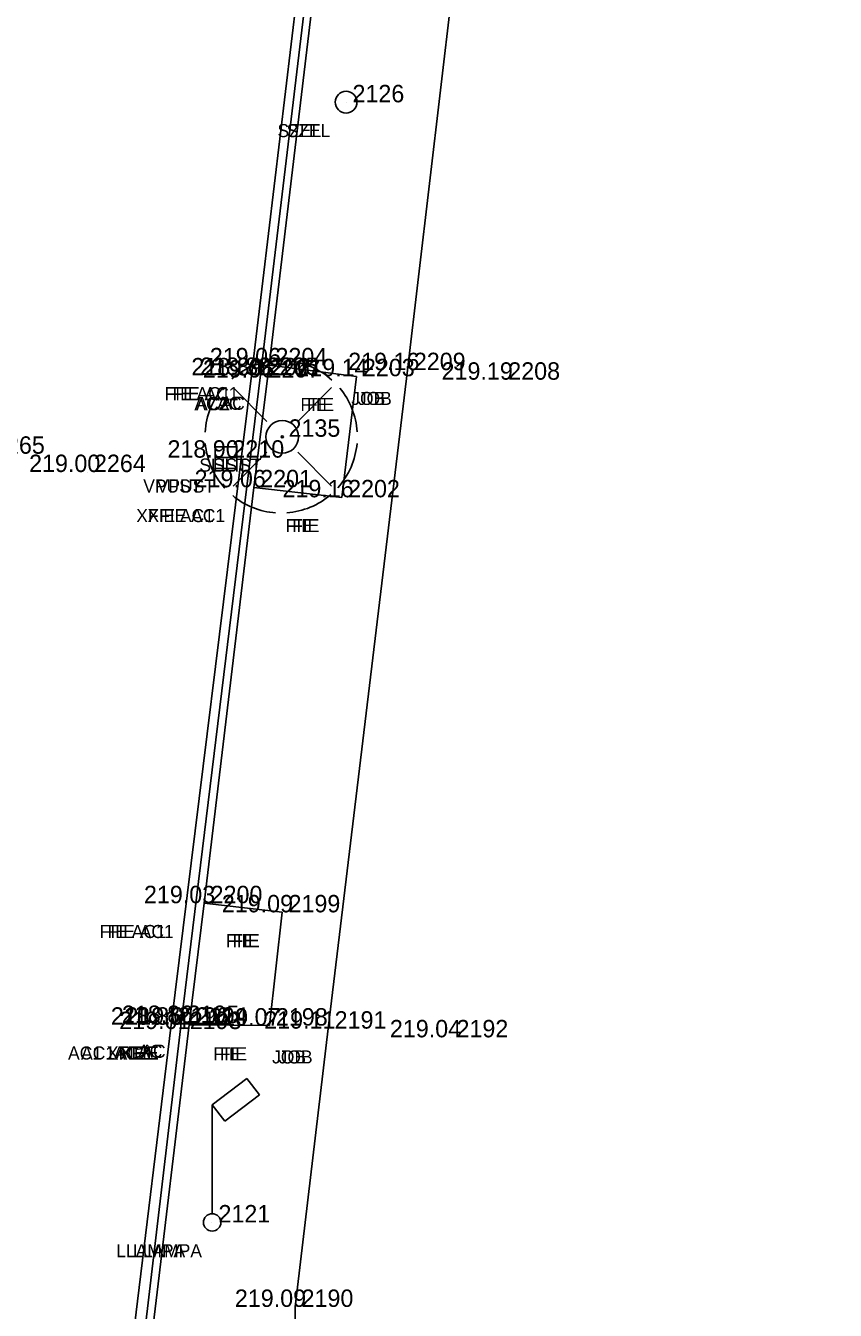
# Model space of a CAD drawing. Extents: x -471047 to -470889, y -1102859 to -1102000.
# Drawn here: x -470938.1 to -470919.5, y -1102294.05 to -1102264.55 of the extents above; entities that cross this region are included whole.
import ezdxf

# ---------------------------------------------------------------- set-up
doc = ezdxf.new("R2010")
doc.units = 0
for name, color, linetype in [('Vrstva 1', 7, 'Continuous'), ('Vrstva 16', 7, 'Continuous'), ('Vrstva 23', 7, 'Continuous'), ('Vrstva 25', 7, 'Continuous'), ('Vrstva 34', 7, 'Continuous'), ('Vrstva 35', 7, 'Continuous'), ('Vrstva 36', 7, 'Continuous'), ('Vrstva 38', 7, 'Continuous'), ('Vrstva 5', 7, 'Continuous'), ('Vrstva 7', 7, 'Continuous'), ('Vrstva 8', 7, 'Continuous')]:
    doc.layers.add(name, color=color, linetype=linetype)

msp = doc.modelspace()

# ---------------------------------------------------------------- linework, layer by layer
at = {"layer": 'Vrstva 1'}
for points in [[(-471040.344, -1102858.385), (-471031.676, -1102846.187), (-471026.357, -1102838.629), (-471023.212, -1102833.975), (-471019.21, -1102827.465), (-471016.861, -1102823.272), (-471013.099, -1102815.912), (-471010.824, -1102810.955), (-471007.329, -1102802.292), (-471005.34, -1102796.515), (-471002.842, -1102787.838), (-471001.3, -1102780.997), (-471000.19, -1102774.713), (-470999.247, -1102768.204), (-470998.794, -1102764.784), (-470997.199, -1102751.812), (-470994.899, -1102732.807), (-470992.551, -1102713.262), (-470990.326, -1102694.887), (-470988.122, -1102676.57), (-470985.812, -1102657.305), (-470983.537, -1102638.407), (-470981.386, -1102620.622), (-470979.843, -1102608.014), (-470976.377, -1102579.253), (-470972.945, -1102550.69), (-470970.475, -1102530.206), (-470967.905, -1102508.801), (-470965.053, -1102485.131), (-470962.734, -1102465.9), (-470960.173, -1102444.812), (-470957.795, -1102425.103), (-470954.965, -1102401.839), (-470953.834, -1102392.574), (-470952.33, -1102379.985), (-470950.744, -1102366.853), (-470948.978, -1102352.106), (-470947.037, -1102335.844), (-470944.949, -1102318.462), (-470944.013, -1102310.745), (-470942.39, -1102297.267), (-470939.519, -1102273.45), (-470937.593, -1102257.43), (-470936.064, -1102244.81), (-470934.114, -1102228.634), (-470931.621, -1102207.856), (-470929.536, -1102190.857), (-470926.572, -1102166.31), (-470924.91, -1102152.663), (-470923.413, -1102140.333), (-470921.923, -1102127.669), (-470921.155, -1102120.084), (-470920.446, -1102109.574), (-470919.912, -1102099.137), (-470919.63, -1102088.981), (-470919.523, -1102081.193), (-470919.563, -1102070.395), (-470919.714, -1102064.236), (-470920.134, -1102054.704), (-470920.462, -1102047.615), (-470920.599, -1102044.52), (-470920.743, -1102041.873), (-470921.125, -1102034.455), (-470921.774, -1102030.337), (-470922.418, -1102027.787), (-470923.734, -1102023.93), (-470924.872, -1102021.434), (-470926.752, -1102018.182), (-470927.953, -1102016.45), (-470929.616, -1102014.424), (-470932.252, -1102011.756), (-470935.111, -1102009.425), (-470938.391, -1102007.371), (-470942.651, -1102005.401)], [(-471041.328, -1102857.18), (-471032.144, -1102844.242), (-471027.583, -1102837.763), (-471024.388, -1102833.028), (-471020.451, -1102826.6), (-471018.089, -1102822.378), (-471014.542, -1102815.445), (-471012.233, -1102810.418), (-471009.247, -1102803.108), (-471006.795, -1102796.098), (-471004.315, -1102787.532), (-471002.782, -1102780.723), (-471001.674, -1102774.458), (-471000.75, -1102768.095), (-471000.28, -1102764.601), (-470998.692, -1102751.741), (-470996.378, -1102732.635), (-470994.028, -1102713.058), (-470991.808, -1102694.749), (-470989.616, -1102676.447), (-470987.284, -1102657.013), (-470985.031, -1102638.272), (-470982.87, -1102620.431), (-470981.334, -1102607.933), (-470977.881, -1102579.263), (-470974.429, -1102550.492), (-470971.964, -1102530.054), (-470969.391, -1102508.607), (-470966.54, -1102484.984), (-470964.231, -1102465.853), (-470961.679, -1102444.752), (-470959.304, -1102425.078), (-470956.455, -1102401.634), (-470955.339, -1102392.489), (-470953.812, -1102379.71), (-470952.249, -1102366.808), (-470950.479, -1102352.023), (-470948.536, -1102335.868), (-470946.426, -1102318.233), (-470945.493, -1102310.531), (-470943.864, -1102297.013), (-470940.984, -1102273.071), (-470939.078, -1102257.195), (-470937.559, -1102244.684), (-470935.592, -1102228.353), (-470933.101, -1102207.653), (-470931.011, -1102190.57), (-470928.046, -1102166.021), (-470926.409, -1102152.578), (-470924.898, -1102140.121), (-470923.427, -1102127.544), (-470922.647, -1102119.826), (-470921.919, -1102109.229), (-470921.42, -1102099.134), (-470921.127, -1102089.016), (-470921.023, -1102081.453), (-470921.061, -1102070.468), (-470921.209, -1102064.314), (-470921.666, -1102053.966), (-470922.156, -1102043.345), (-470922.299, -1102039.934), (-470922.637, -1102034.36), (-470923.091, -1102031.241), (-470923.847, -1102028.247), (-470925.083, -1102024.594), (-470926.222, -1102022.086), (-470928.04, -1102018.943), (-470929.138, -1102017.357), (-470930.929, -1102015.175), (-470933.062, -1102013.049), (-470936.379, -1102010.368), (-470939.169, -1102008.662), (-470942.899, -1102006.906), (-470945.661, -1102005.908)], [(-471043.557, -1102855.955), (-471035.129, -1102844.026), (-471029.872, -1102836.499), (-471026.577, -1102831.578), (-471022.675, -1102825.415), (-471020.123, -1102821.053), (-471016.667, -1102814.59), (-471014.208, -1102809.45), (-471011.177, -1102802.451), (-471008.55, -1102795.333), (-471006.082, -1102787.209), (-471004.464, -1102780.376), (-471003.265, -1102774.167), (-471002.327, -1102767.948), (-471001.636, -1102762.527), (-471000.297, -1102751.605), (-470997.959, -1102732.524), (-470995.602, -1102712.802), (-470993.412, -1102694.623), (-470991.21, -1102676.17), (-470988.891, -1102656.857), (-470986.625, -1102638.083), (-470984.455, -1102620.195), (-470982.936, -1102607.733), (-470979.497, -1102579.223), (-470976.023, -1102550.279), (-470973.554, -1102529.822), (-470970.991, -1102508.497), (-470968.146, -1102484.787), (-470965.835, -1102465.72), (-470963.284, -1102444.529), (-470960.91, -1102424.942), (-470958.043, -1102401.343), (-470956.946, -1102392.356), (-470955.396, -1102379.408), (-470953.851, -1102366.636), (-470952.049, -1102351.733), (-470950.124, -1102335.611), (-470948.034, -1102318.083), (-470947.094, -1102310.328), (-470945.421, -1102296.51), (-470942.58, -1102272.848), (-470940.675, -1102256.948), (-470939.176, -1102244.526), (-470937.187, -1102228.174), (-470934.708, -1102207.467), (-470932.621, -1102190.433), (-470929.634, -1102165.778), (-470928.004, -1102152.415), (-470926.45, -1102139.595), (-470925.003, -1102127.418), (-470924.249, -1102119.695), (-470923.515, -1102109.093), (-470923.018, -1102099.069), (-470922.711, -1102088.911), (-470922.643, -1102081.356), (-470922.797, -1102070.414), (-470923.018, -1102064.454), (-470923.52, -1102053.203), (-470923.823, -1102047.529), (-470924.123, -1102041.506), (-470924.462, -1102037.486), (-470924.934, -1102031.904), (-470925.664, -1102028.672), (-470926.771, -1102025.506), (-470927.959, -1102022.914), (-470929.674, -1102020.028), (-470930.76, -1102018.498), (-470932.447, -1102016.478), (-470935.215, -1102013.816), (-470937.644, -1102011.98), (-470940.381, -1102010.371), (-470943.968, -1102008.669), (-470947.145, -1102007.524), (-470950.874, -1102006.74)], [(-471044.756, -1102855.056), (-471036.376, -1102843.177), (-471031.167, -1102835.741), (-471027.859, -1102830.8), (-471023.934, -1102824.593), (-471021.43, -1102820.312), (-471018.011, -1102813.91), (-471015.536, -1102808.75), (-471012.578, -1102801.897), (-471009.95, -1102794.77), (-471007.561, -1102786.914), (-471005.936, -1102780.074), (-471004.727, -1102773.818), (-471003.828, -1102767.827), (-471003.121, -1102762.345), (-471001.787, -1102751.467), (-470999.446, -1102732.348), (-470997.073, -1102712.539), (-470994.902, -1102694.521), (-470992.696, -1102676.023), (-470990.376, -1102656.68), (-470988.131, -1102638.071), (-470985.947, -1102620.018), (-470984.417, -1102607.512), (-470980.993, -1102579.08), (-470977.514, -1102550.137), (-470975.048, -1102529.649), (-470972.488, -1102508.37), (-470969.618, -1102484.508), (-470967.34, -1102465.669), (-470964.767, -1102444.39), (-470962.402, -1102424.781), (-470959.534, -1102401.193), (-470958.432, -1102392.151), (-470956.883, -1102379.208), (-470955.335, -1102366.424), (-470953.535, -1102351.506), (-470951.606, -1102335.399), (-470949.519, -1102317.94), (-470948.575, -1102310.159), (-470946.889, -1102296.144), (-470944.056, -1102272.618), (-470942.139, -1102256.659), (-470940.657, -1102244.341), (-470938.638, -1102227.749), (-470936.19, -1102207.298), (-470934.102, -1102190.255), (-470931.124, -1102165.639), (-470929.492, -1102152.254), (-470927.915, -1102139.252), (-470926.46, -1102127.103), (-470925.74, -1102119.604), (-470925.012, -1102108.913), (-470924.523, -1102099.054), (-470924.217, -1102088.866), (-470924.148, -1102081.334), (-470924.301, -1102070.391), (-470924.518, -1102064.43), (-470924.97, -1102054.435), (-470925.588, -1102041.569), (-470925.963, -1102035.313), (-470926.405, -1102032.225), (-470927.078, -1102029.198), (-470928.123, -1102026.148), (-470929.318, -1102023.558), (-470930.84, -1102020.97), (-470931.868, -1102019.515), (-470933.443, -1102017.605), (-470936.26, -1102014.885), (-470938.429, -1102013.255), (-470941.213, -1102011.639), (-470944.847, -1102009.927), (-470947.723, -1102008.912), (-470951.444, -1102008.161), (-470954.511, -1102007.931), (-470957.895, -1102008.041)]]:
    msp.add_spline(points, degree=3, dxfattribs=at)
at = {"layer": 'Vrstva 16'}
for p, q in [((-470932.56, -1102273.636), (-470933.336, -1102272.861)), ((-470931.85, -1102273.636), (-470931.076, -1102272.861)), ((-470932.56, -1102274.346), (-470933.336, -1102275.121)), ((-470931.85, -1102274.346), (-470931.076, -1102275.121))]:
    msp.add_line(p, q, dxfattribs=at)
for radius in [0.375, 0.025, 0.025]:
    msp.add_circle((-470932.205, -1102273.991), radius, dxfattribs=at)
for start, end in [(96.7144, 130.447), (48.1897, 84.9117), (139.23, 176.4602), (3.8615, 39.6013), (184.9408, 222.2827), (318.1086, 355.0481), (274.1732, 310.7861), (230.4703, 265.8356)]:
    msp.add_arc((-470932.231, -1102273.991), 1.75, start, end, dxfattribs=at)
at = {"layer": 'Vrstva 23'}
for p, q in [((-470933.021, -1102288.725), (-470933.816, -1102289.33)), ((-470932.731, -1102289.102), (-470933.021, -1102288.725)), ((-470933.528, -1102289.708), (-470932.731, -1102289.102)), ((-470933.816, -1102289.33), (-470933.816, -1102291.83)), ((-470933.816, -1102289.33), (-470933.528, -1102289.708))]:
    msp.add_line(p, q, dxfattribs=at)
for centre, radius in [((-470930.739, -1102266.306), 0.25), ((-470933.816, -1102292.03), 0.2)]:
    msp.add_circle(centre, radius, dxfattribs=at)
at = {"layer": 'Vrstva 25'}
for p, q in [((-470933.747, -1102274.219), (-470933.747, -1102274.719)), ((-470933.247, -1102274.219), (-470933.747, -1102274.219)), ((-470933.247, -1102274.719), (-470933.247, -1102274.219)), ((-470933.747, -1102274.469), (-470933.247, -1102274.469)), ((-470933.747, -1102274.719), (-470933.247, -1102274.719))]:
    msp.add_line(p, q, dxfattribs=at)
at = {"layer": 'Vrstva 34'}
for p, q in [((-470930.74, -1102266.31), (-470930.74, -1102266.31)), ((-470932.51, -1102272.35), (-470932.51, -1102272.35)), ((-470932.91, -1102272.58), (-470932.91, -1102272.58)), ((-470932.71, -1102272.57), (-470932.71, -1102272.57)), ((-470932.67, -1102272.63), (-470932.67, -1102272.63)), ((-470930.5, -1102272.6), (-470930.5, -1102272.6)), ((-470929.33, -1102272.46), (-470929.33, -1102272.46)), ((-470927.16, -1102272.68), (-470927.16, -1102272.68)), ((-470932.21, -1102273.99), (-470932.21, -1102273.99)), ((-470933.5, -1102274.47), (-470933.5, -1102274.47)), ((-470936.68, -1102274.8), (-470936.68, -1102274.8)), ((-470932.86, -1102275.15), (-470932.86, -1102275.15)), ((-470930.84, -1102275.38), (-470930.84, -1102275.38)), ((-470934, -1102284.7), (-470934, -1102284.7)), ((-470932.21, -1102284.91), (-470932.21, -1102284.91)), ((-470934.76, -1102287.49), (-470934.76, -1102287.49)), ((-470934.53, -1102287.45), (-470934.53, -1102287.45)), ((-470934.48, -1102287.59), (-470934.48, -1102287.59)), ((-470934.34, -1102287.49), (-470934.34, -1102287.49)), ((-470932.5, -1102287.51), (-470932.5, -1102287.51)), ((-470931.15, -1102287.58), (-470931.15, -1102287.58)), ((-470928.35, -1102287.78), (-470928.35, -1102287.78)), ((-470933.82, -1102292.03), (-470933.82, -1102292.03)), ((-470931.91, -1102293.97), (-470931.91, -1102293.97))]:
    msp.add_line(p, q, dxfattribs=at)
at = {"layer": 'Vrstva 5'}
for p, q in [((-470932.914, -1102272.583), (-470930.979, -1102256.399)), ((-470934.761, -1102287.492), (-470932.914, -1102272.583)), ((-470937.416, -1102309.267), (-470934.761, -1102287.492))]:
    msp.add_line(p, q, dxfattribs=at)
at = {"layer": 'Vrstva 7'}
for p, q in [((-470932.505, -1102272.345), (-470930.626, -1102256.58)), ((-470932.856, -1102275.152), (-470932.505, -1102272.345)), ((-470934.001, -1102284.703), (-470932.856, -1102275.152)), ((-470934.345, -1102287.49), (-470934.001, -1102284.703)), ((-470936.738, -1102307.442), (-470934.345, -1102287.49))]:
    msp.add_line(p, q, dxfattribs=at)
at = {"layer": 'Vrstva 8'}
for p, q in [((-470932.707, -1102272.566), (-470930.771, -1102256.476)), ((-470929.325, -1102272.464), (-470927.565, -1102257.461)), ((-470930.498, -1102272.604), (-470932.505, -1102272.345)), ((-470934.525, -1102287.454), (-470932.707, -1102272.566)), ((-470931.147, -1102287.579), (-470929.325, -1102272.464)), ((-470930.837, -1102275.383), (-470930.498, -1102272.604)), ((-470932.856, -1102275.152), (-470930.837, -1102275.383)), ((-470932.207, -1102284.905), (-470934.001, -1102284.703)), ((-470932.5, -1102287.507), (-470932.207, -1102284.905)), ((-470937.151, -1102309.5), (-470934.525, -1102287.454)), ((-470934.345, -1102287.49), (-470932.5, -1102287.507)), ((-470931.91, -1102293.966), (-470931.147, -1102287.579)), ((-470931.902, -1102294.602), (-470931.91, -1102293.966))]:
    msp.add_line(p, q, dxfattribs=at)

# ---------------------------------------------------------------- texts
at = {"layer": 'Vrstva 35'}
for s, p in [('SZEL', (-470932.315, -1102267.11)), ('SZEL', (-470932.104, -1102267.11)), ('FIE AC1', (-470934.91, -1102273.15)), ('FIE AC1', (-470934.727, -1102273.15)), ('JOB', (-470930.619, -1102273.26)), ('JOB', (-470930.469, -1102273.26)), ('AC2', (-470934.226, -1102273.38)), ('AC2', (-470934.185, -1102273.38)), ('AC', (-470933.699, -1102273.37)), ('AC', (-470933.624, -1102273.37)), ('FIE', (-470931.788, -1102273.4)), ('FIE', (-470931.639, -1102273.4)), ('SLIST', (-470934.11, -1102274.79)), ('SLIST', (-470933.799, -1102274.79)), ('VPUST', (-470935.4, -1102275.27)), ('VPUST', (-470935.089, -1102275.27)), ('XFIE AC1', (-470935.56, -1102275.95)), ('XFIE AC1', (-470935.302, -1102275.95)), ('FIE', (-470932.128, -1102276.18)), ('FIE', (-470931.979, -1102276.18)), ('FIE AC1', (-470936.4, -1102285.5)), ('FIE AC1', (-470936.217, -1102285.5)), ('FIE', (-470933.497, -1102285.71)), ('FIE', (-470933.349, -1102285.71)), ('AC1 XFIE', (-470937.128, -1102288.29)), ('AC1 XFIE', (-470936.829, -1102288.29)), ('AC2', (-470936.076, -1102288.29)), ('AC2', (-470936.035, -1102288.29)), ('AC', (-470935.519, -1102288.25)), ('AC', (-470935.444, -1102288.25)), ('FIE', (-470933.788, -1102288.31)), ('FIE', (-470933.639, -1102288.31)), ('JOB', (-470932.439, -1102288.38)), ('JOB', (-470932.289, -1102288.38)), ('LLAMPA', (-470936.02, -1102292.83)), ('LLAMPA', (-470935.634, -1102292.83))]:
    msp.add_text(s, height=0.3, dxfattribs=at).set_placement(p)
at = {"layer": 'Vrstva 36'}
for s, p in [(' 2126', (-470930.74, -1102266.31)), (' 2204', (-470932.51, -1102272.35)), (' 2209', (-470929.33, -1102272.46)), (' 2206', (-470932.91, -1102272.58)), (' 2205', (-470932.71, -1102272.57)), (' 2207', (-470932.67, -1102272.63)), (' 2203', (-470930.5, -1102272.6)), (' 2208', (-470927.16, -1102272.68)), (' 2135', (-470932.21, -1102273.99)), (' 2265', (-470939, -1102274.38)), (' 2210', (-470933.5, -1102274.47)), (' 2264', (-470936.68, -1102274.8)), (' 2201', (-470932.86, -1102275.15)), (' 2202', (-470930.84, -1102275.38)), (' 2200', (-470934, -1102284.7)), (' 2199', (-470932.21, -1102284.91)), (' 2196', (-470934.76, -1102287.49)), (' 2195', (-470934.53, -1102287.45)), (' 2194', (-470934.34, -1102287.49)), (' 2198', (-470932.5, -1102287.51)), (' 2193', (-470934.48, -1102287.59)), (' 2191', (-470931.15, -1102287.58)), (' 2192', (-470928.35, -1102287.78)), (' 2121', (-470933.82, -1102292.03)), (' 2190', (-470931.91, -1102293.97))]:
    msp.add_text(s, height=0.4, dxfattribs=at).set_placement(p)
at = {"layer": 'Vrstva 38'}
for s, p in [('219.06 ', (-470933.87, -1102272.35)), ('219.16 ', (-470930.69, -1102272.46)), ('218.89 ', (-470934.294, -1102272.58)), ('218.88 ', (-470934.094, -1102272.57)), ('219.06 ', (-470934.03, -1102272.63)), ('219.14 ', (-470931.882, -1102272.6)), ('219.19 ', (-470928.544, -1102272.68)), ('218.90 ', (-470934.843, -1102274.47)), ('219.00 ', (-470938.023, -1102274.8)), ('219.06 ', (-470934.22, -1102275.15)), ('219.16 ', (-470932.2, -1102275.38)), ('219.03 ', (-470935.383, -1102284.7)), ('219.09 ', (-470933.594, -1102284.91)), ('218.85 ', (-470936.144, -1102287.49)), ('218.86 ', (-470935.89, -1102287.45)), ('219.01 ', (-470935.81, -1102287.49)), ('219.07 ', (-470933.883, -1102287.51)), ('219.01 ', (-470935.95, -1102287.59)), ('219.11 ', (-470932.62, -1102287.58)), ('219.04 ', (-470929.732, -1102287.78)), ('219.09 ', (-470933.294, -1102293.97))]:
    msp.add_text(s, height=0.4, dxfattribs=at).set_placement(p)

doc.saveas('drawing.dxf')
